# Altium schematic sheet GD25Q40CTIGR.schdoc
size 127 x 101 mm
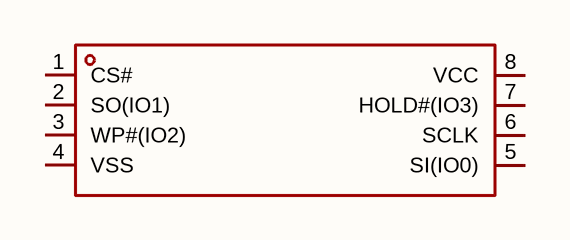
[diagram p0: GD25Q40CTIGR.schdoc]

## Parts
U?  gd25q40ctigr  [SOP-8_L4.9-W3.9-P1.27-LS6.0-BL]  (value not drawn)

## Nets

Not connected (* = marked no-connect by the designer): U? 1(CS#) 2(SO(IO1)) 3(WP#(IO2)) 4(VSS) 5(SI(IO0)) 6(SCLK) 7(HOLD#(IO3)) 8(VCC)

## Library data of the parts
U? = gd25q40ctigr: 接口类型:SPI;存储容量:4Mbit;; Manufacturer: GigaDevice(兆易创新); AddInBom: yes; ModelId: 75c24a7891ee4dd6bdac16a7163ff87e; ModelName: SOP-8_L4.9-W3.9-P1.27-LS6.0-BL-1; ModelTransform: 192.913,236.22,0,0,0,0,-0.393,2.749,0; Interface Type: SPI; Memory Size: 4Mbit; Supply Voltage: 2.7V~3.6V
